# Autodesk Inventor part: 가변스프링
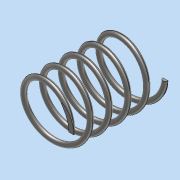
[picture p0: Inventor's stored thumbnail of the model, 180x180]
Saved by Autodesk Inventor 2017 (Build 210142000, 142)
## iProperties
Part Number: 가변스프링
Material: 강철, 연강
Document SubType Name: Modeling
Designer: MRC
Density: 7.85 g/cm^3
Appearance: 반연마
Mass: 8.42795 g
Surface Area: 21.7305 cm^2
Volume: 1.07362 cm^3
Author: MRC
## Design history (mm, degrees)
sketch "스케치1"
  geometry: L1 (0, 0)-(0, 36.411); L2 (0, 0)-(11, 0); L3 (0, 36.411)-(11, 36.411); C1 r 1 at (11, 0)
  constraints: 6 end point, 2 horizontal, 1 centre point, 1 coincident, 1 vertical
  dimensions: "d0" = 36.4112 distance of L1.start L1.end (derived); "d1" = 11 distance of L1.start L2.end; "d2" = 2 diameter of C1
feature "코일1" pitch "d3" = 10; turns "d5" = 5; dims "d4" = 36.4112 (= d0), "d6" = 0, angle "d7" = 90 deg, angle "d8" = 90 deg, "d9" = 0, "d10" = 0
sketch "스케치2"
  geometry: L1 (36.411, 15)-(0, 15); L2 (0, 15)-(0, -15); L3 (0, -15)-(36.411, -15); L4 (36.411, -15)-(36.411, 15); 2 further points
  constraints: 8 end point, 2 parallel, 1 coincident, 1 horizontal, 1 midpoint, 1 perpendicular
  dimensions: "d11" = 30 distance of L3.end L1.start; "d12" = 36.4112 distance of L2.end L3.end (= d0)
extrude "돌출1" sketch "스케치2" stored distance "d13" = 30; taper "d14" = 0 deg
node "솔리드1"
